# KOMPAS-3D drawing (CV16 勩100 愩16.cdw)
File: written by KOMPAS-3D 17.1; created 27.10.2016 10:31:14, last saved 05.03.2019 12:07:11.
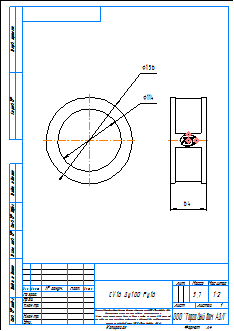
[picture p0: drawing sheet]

Sheet 1: A4, portrait

Title block, sheet 1: name: CV16 Ду100 Ру16; material: Сталь 20  ГОСТ 1050-88; mass: 5,7; sheets: 1; sheet format: A4; stored path: \\adlc.lan\data\АДЛ_ПКД\3D-модели\ADL production\Клапаны обратные ГРАНЛОК\CV16\KOMPAS 2D\CV16 Ду100 Ру16.cdw

Views: Вид 1, Проекционный вид 2
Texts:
  Klimkovich
  ADL
  Рама для чертежей
  Лит-Масса-Масштаб
  Материал-Предприятие
  Масштаб
  Изм.
  Лист
  № докум.
  Подп.
  Дата
  Лит.
  Разраб.
  Пров.
  Т.контр.
  Листов
  Внимание! Данный продукт является объектом авторского права ООО «Торговый Дом АДЛ».
  Запрещается изменение, копирование, распространение
  (в том числе путем копирования на другие сайты и ресурсы в Интернете)
  или любое иное использование информации и объектов без предварительного
  согласия правообладателя (ООО «Торговый Дом АДЛ»).
  Н.контр.
  Утв.
  ООО "Торговый дом АДЛ"
  Изменение
  Номер документа
  Подпись
  Обозначение документа
  Наименование изделия
  Масса изделия по ГОСТ 2.109-73
  Порядковый номер листа
  Общее количество листов в документе
  Характер работы, выполненной лицом, подписавшим документ
  Наименование или индекс предприятия, выпускающего документ
  Инв. № подл.
  Подп. и дата
  Взам. инв. №
  Инв. № дубл.
  Инвентарный номер подлинника по ГОСТ 2.501-68
  Подпись принявшего подлинник в отдел технической документации
  Инвентарный номер подлинника, взамен которого выпущен данный подлинник
  Инвентарный номер дубликата по ГОСТ 2.502-68
  Подпись принявшего дубликат в отдел технической документации
  Справ. №
  Перв. примен.
  Обозначение документа, взамен или на основании которого выпущен данный документ
  Обозначение документа, в котором впервые записан данный документ
  Подпись лица, копировавшего чертеж
  Обозначение формата листа
  !Рама для чертежа
Dimensions and other numbers on the sheet: 156; 114; 64; 1:2; 1; 5,7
